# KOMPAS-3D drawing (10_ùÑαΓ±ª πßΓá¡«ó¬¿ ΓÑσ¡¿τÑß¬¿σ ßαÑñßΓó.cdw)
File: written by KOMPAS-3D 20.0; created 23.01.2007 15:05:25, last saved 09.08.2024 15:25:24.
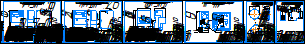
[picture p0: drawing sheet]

Sheets 1-4: A3, landscape
Sheets 5-6: A4, portrait

Document properties: Автор: Семёнов; Организация: СиТ; Разработал: Антошин; Проверил: Тарасов; Утвердил: Шмончев; Н. контр.: Силаков; Форматы листов документа: 2xA4, 4xA3

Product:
- Part/product: (unnamed)
  - Component: \\Helios\отдел_пко\Общая папка Компас\_Addons\Signatures\Signatures.lfr|Шмончев  | Полное имя файла: C:\Users\MAntoshin\AppData\Local\Temp\hsklda.frw; source file: C:\Program Files\ASCON\KOMPAS-3D V13\Libs\_Addons\Signatures\Signatures.lfr
  - Component: \\Helios\отдел_пко\Общая папка Компас\_Addons\Signatures\Signatures.lfr|Силаков  | Полное имя файла: C:\Users\MAntoshin\AppData\Local\Temp\eiczbt.frw; source file: C:\Program Files\ASCON\KOMPAS-3D V13\Libs\_Addons\Signatures\Signatures.lfr
  - Component: \\Helios\отдел_пко\Общая папка Компас\_Addons\Signatures\Signatures.lfr|Тарасов  | Полное имя файла: C:\Users\MAntoshin\AppData\Local\Temp\qlkzkl.frw; source file: C:\Program Files\ASCON\KOMPAS-3D V13\Libs\_Addons\Signatures\Signatures.lfr

Title block, sheet 1: designation: ВЛСТ 1277.02.000 СА; sheet number: 1; Количество листов документа: 30; organisation: АО ГК / "Системы и Технологии"; Форматы листов документа: A3; stored path: \\Helios\departments\Отдел_ПКО\Проекты\Бийский Олеумный Завод\Проект\2_Рабочая документация\1_ГПП-2\СА_001_01_Чертёж установки технических средств.cdw; cell 302: Система учета электроэнергии (с организацией удаленного сбора данных) / потребителей; cell 303: Типовой проект ИСУЭ / многоквартирного дома с использованием / радиоканала (F2/868 МГц); cell 304: Чертеж установки / технических средств; cell 320: Р
Title block, sheet 2: sheet number: 2; sheet number: 7; Форматы листов документа: A4; stored path: \\s-tech\depts\Отдел_ПКО\Проекты\Типовые проекты МКД 2023\!Типовой проект\1_Типовой проект МКД_RS-485\_Чертёж установки технических средств.cdw
Title block, sheet 3: sheet number: 3
Title block, sheet 4: sheet number: 4; stored path: \\Helios\отдел_пко\Проекты\МРСК Северо-Запада Псковэнерго\Проект\02-07_Рабочая документация\04_Многоквартирный дом,Г.Псков, ул. Юбилейная д.42\СА_001_Чертёж установки технических средств.cdw
Title block, sheet 5: sheet number: 5; stored path: \\s-tech\depts\Отдел_ПКО\Проекты\Типовые проекты МКД 2023\!Типовой проект\2_Типовой проект МКД_Радиоканал\10_Чертёж установки технических средств.cdw
Title block, sheet 6: sheet number: 6; designation, second copy: ВЛСТ 1277.02.000 СА-

Referenced files in \\Helios\отдел_пко\Общая папка Компас\_Addons\Signatures\: Signatures.lfr|Тарасов, Signatures.lfr, Signatures.lfr|Силаков, Signatures.lfr|Шмончев
Referenced files in C:\Program Files\ASCON\KOMPAS-3D V13\Libs\_Addons\Signatures\: Signatures.lfr
Referenced files: qlkzkl.frw, eiczbt.frw, hsklda.frw
Referenced files in C:\Program Files\ASCON\KOMPAS-3D v20\Sys\: Lighting.lts
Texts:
  Тарасов
  Силаков
  Шмончев
  Normal
  Термин
  Список определений
  Адреса
  Цитаты
  Готовый
  Courier New
  z-Bottom of Form
  z-Top of Form
  Лит-Масса-Масштаб
  Материал-Предприятие
  Z-начало формы
  Z-конец формы
  Форматированный
  Адрес
  Обычный
  heading 2
  Body Text
  heading 1
  Без имени
  txt
  footer
  heading 8
  Centerline
  Outline
  Счетчик электрической энергии однофазный КВАНТ ST1000-9-W
  Присоединительные и установочные размеры
  1. Размеры для справок.
  2. При монтаже оборудования необходимо использовать специализированные наборы для
  крепления оборудования.
  3. При установке счетчика  КВАНТ ST1000-9 необходимо руководствоваться правилами «ПУЭ»
  (седьмое издание, глава 1.5) и руководством по эксплутации счетчика  КВАНТ ST1000-9
  ВЛСТ.418.00.000 РЭ.
  4. Пломбирование счетчика  КВАНТ ST1000-9 производить скрученной проволокой пломбировочной и свинцовой пломбой
  диаметром 10мм. Либо самоклеющейся номерной разрушаемой пломбой.
  Счетчик электрической энергии трехфазный прямого включения КВАНТ ST2000-12
  1. При монтаже оборудования необходимо использовать специализированные наборы для
  2. При установке счетчика  КВАНТ ST2000-12 необходимо руководствоваться правилами «ПУЭ»
  (седьмое издание, глава 1.5) и руководством по эксплутации счетчика  КВАНТ ST2000-12
  ВЛСТ.419.00.000 РЭ.
  3. Пломбирование счетчика  КВАНТ ST1000-12 производить скрученной проволокой пломбировочной и свинцовой пломбой
  Счетчик электрической энергии однофазный КВАНТ ST1000-9-W2
  2. При установке счетчика  КВАНТ ST1000-9 необходимо руководствоваться правилами «ПУЭ»
  3. Пломбирование счетчика  КВАНТ ST1000-9 производить скрученной проволокой пломбировочной и свинцовой пломбой
  RF-формирователь Link ST200.F2-09-SMA "повторитель" (ВЛСТ 339.04.000-9s)
  Габаритные размеры
  Крышка
  Маркировка
  Автоматический выключатель BA 47-29 2Р 6А
  Габаритные, присоединительные и установочные размеры
  Разветвительная коробка RS-485
  Проволока
  Пломба
  POLYLINE_STYLE_0.25_RGB_0_0_0
  ANSI37
  Разраб.
  Антошин
  Чертёж установки
  03 Рабочие чертежи основного комплекта. ГОСТ Р 21.1101-2009 Ф3
  05 Чертежи строительных изделий. Посл. листы. ГОСТ Р 21.1101-2009 Ф6
Dimensions and other numbers on the sheet: 35; 2; 168; 75; 130; 150; 107; 6; 10; 252; 176; 93; 158; 220; 12; 5; 138; 62,5; 73; 90; 45; 50; 36; 74,43; 36,49; 77,46; 34,29; 2 отв.; 4; 88; 40; 1; 02.23; 30; 7; 3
